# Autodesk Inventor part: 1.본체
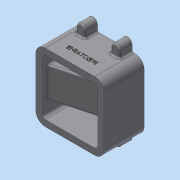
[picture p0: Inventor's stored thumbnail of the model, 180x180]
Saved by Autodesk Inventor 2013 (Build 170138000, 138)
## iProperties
Created: 2018-01
Part Number: 1.본체
Material: 일반
Document SubType Name: Modeling
Designer: dgall
Density: 1 g/cm^3
Author: dgall
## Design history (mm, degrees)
sketch "스케치1"
  geometry: L1 (-55, 55)-(55, 55); L2 (55, 55)-(55, -55); L3 (55, -55)-(-55, -55); L4 (-55, -55)-(-55, 55); 3 further points
  constraints: 8 end point, 2 midpoint, 2 parallel, 2 perpendicular, 1 horizontal, 1 horizontal alignment, 1 vertical alignment
  dimensions: "d1" = 110 distance of L1.start L1.end
extrude "돌출1" new body sketch "스케치1" distance "d3" = 65; taper "d4" = 0 deg
sketch "스케치2"
  geometry: L1 (-55, -55)-(55, -55) reference; L2 (55, -55)-(55, 55) reference; L3 (55, 55)-(-55, 55) reference; L4 (-55, 55)-(-55, -55) reference; L5 (-45, 45)-(45, 45); L6 (45, 45)-(45, -45); L7 (45, -45)-(-45, -45); L8 (-45, -45)-(-45, -25); L9 (-45, -25)-(35, -25); L10 (35, -25)-(35, 25); L11 (35, 25)-(-45, 25); L12 (-45, 25)-(-45, 45); 1 further point
  constraints: 16 end point, 6 parallel, 2 perpendicular, 1 collinear, 1 vertical alignment
  dimensions: "d5" = 10 distance between parallel lines of L4 L12; "d6" = 20 distance between parallel lines of L2 L10; "d7" = 10 distance between parallel lines of L2 L6; "d8" = 10 distance between parallel lines of L1 L7; "d9" = 10 distance between parallel lines of L3 L5; "d10" = 50 distance between parallel lines of L9 L11
extrude "돌출2" cut sketch "스케치2" distance "d11" = 65; taper "d12" = 0 deg
sketch "스케치3"
  geometry: L1 (80, -65)-(0, -65) reference; L2 (80, 0)-(80, -65) reference; L3 (0, -65)-(0, -56.436); L4 (0, -56.436)-(80, -35); L5 (-10, -65)-(-10, 0) reference; 1 further point
  constraints: 4 end point, 2 point on line, 1 perpendicular
  dimensions: "d13" = 30 distance of L1.start L4.end; "d14" = 105 deg angle of L3 L4; "d15" = 10 distance between parallel lines of L5 L3
extrude "돌출3" cut sketch "스케치3" distance "d16" = 65; taper "d17" = 0 deg
node "작업 평면1"
sketch "스케치4"
  geometry: L1 (0, 0)-(0, -56.436) reference; L2 (100, 0)-(-10, 0) reference; L3 (-10, 0)-(100, 0); L4 (-10, 0)-(-10, -7.5); L5 (-10, -7.5)-(9, -7.5); L6 (9, -7.5)-(9, -16); L7 (9, -16)-(23, -16); L8 (23, -16)-(23, -20); L9 (23, -20)-(70, -20); L10 (70, -20)-(70, -15); L11 (70, -15)-(75, -15); L12 (75, -15)-(75, 0); 1 further point
  constraints: 20 end point, 6 parallel, 3 perpendicular, 1 collinear, 1 point on line
  dimensions: "d18" = 15 diameter of L5 L2; "d19" = 32 diameter of L7 L2; "d20" = 40 diameter of L9 L2; "d21" = 30 diameter of L11 L2; "d22" = 5 distance of L10.end L11.end; "d23" = 47 distance of L8.end L9.end; "d24" = 14 distance of L6.end L7.end; "d25" = 19 distance of L4.end L5.end
revolve "회전1" sketch "스케치4" stored, may be unused: angle "d26" = 90 deg
sketch "스케치5"
  geometry: L1 (23, 0)-(70, 0) reference; L2 (23, 0)-(23, 0) reference; L3 (70, 0)-(23, 0) reference; L4 (70, 0)-(70, 0) reference; L5 (23, -20)-(70, -20) reference; L6 (-10, -65)-(-10, 0) reference; L7 (28, -25.757)-(-10, -35.939); L8 (-10, -53.939)-(65, -33.843); L9 (80, -35)-(0, -56.436) reference; L10 (70, -20)-(70, 0) reference; L11 (28, -25.757)-(28, 0); L12 (65, -33.843)-(65, 0); L13 (23, -20)-(23, 0) reference; 1 further point
  constraints: 8 end point, 4 point on line, 3 parallel, 1 perpendicular
  dimensions: "d28" = 18 distance of L8.start L7.end; "d29" = 5 distance between parallel lines of L9 L8; "d31" = 5 distance between parallel lines of L12 L10; "d32" = 5 distance between parallel lines of L13 L11
extrude "돌출4" cut sketch "스케치5" stored distance "d33" = 30; taper "d34" = 0 deg
fillet "모깎기1" dims "d35" = 3
fillet "모깎기2" dims "d36" = 3
fillet "모깎기3" dims "d37" = 3
fillet "모깎기4" dims "d38" = 3
fillet "모깎기5" dims "d39" = 15
sketch "스케치6"
  geometry: L1 (40, 55)-(-40, 55) reference; L2 (-55, 40)-(-55, 7.5) reference; L3 (-35.5, 65)-(-35.5, 55); L4 (-20.5, 65)-(-20.5, 55); L5 (20.5, 65)-(20.5, 55); L6 (35.5, 65)-(35.5, 55); A1 r 7.5 centre (-28, 65) between (-35.5, 65) and (-20.5, 65); A2 r 7.5 centre (28, 65) between (20.5, 65) and (35.5, 65); 1 further point
  constraints: 8 end point, 4 perpendicular, 4 point on circle, 4 point on line, 4 tangent, 2 centre point, 1 horizontal alignment
  dimensions: "d40" = 15 diameter of A1; "d41" = 15 diameter of A2; "d42" = 27 distance from line of L2 A1.centre; "d43" = 56 distance of A1.centre A2.centre; "d44" = 10 distance from line of L1 A2.centre
extrude "돌출5" join sketch "스케치6" distance "d45" = 20; taper "d46" = 0 deg
node "작업 평면2"
fillet "모깎기6" dims "d54" = 3
fillet "모깎기7" dims "d55" = 3
fillet "모깎기8" dims "d56" = 1
chamfer "모따기1" distance "d57" = 1; stored, may be unused: second distance "d58" = 2, angle "d59" = 45 deg
chamfer "모따기2" distance "d60" = 1; stored, may be unused: second distance "d61" = 2, angle "d62" = 45 deg
fillet "모깎기9" dims "d63" = 5
sketch "스케치8"
  geometry: L1 (80, 0)-(0, 0) reference; L2 (-15, 65)-(-15, 0) reference; 2 further points
  constraints: 1 other
  dimensions: "d66" = 55 distance from line of L2 point (40, 20); "d67" = 20 distance from line of L1 point (40, 20)
feature "엠보싱1" sketch "스케치8" dims "d1" = 110, "d5" = 10, "d6" = 20, "d7" = 10, "d8" = 10, "d9" = 10, "d10" = 50, "d68" = 0.5, "d69" = 0
fillet "모깎기12" dims "d70" = 3
fillet "모깎기13" dims "d71" = 3
sketch "스케치9"
  geometry: A1 r 7.5 centre (-28, -65) between (-35.5, -65) and (-20.5, -65) reference; A2 r 7.5 centre (28, -65) between (20.5, -65) and (35.5, -65) reference; A3 r 7.5 centre (28, 65) between (35.5, 65) and (20.5, 65) reference; A4 r 7.5 centre (-28, 65) between (-20.5, 65) and (-35.5, 65) reference; 1 further point
hole "구멍2" sketch "스케치9" at (28, 65), (-28, 65), (-28, -65), (28, -65) diameter "d72" = 3.242; stored, may be unused: countersink angle "d76" = 90 deg, drill point angle "d78" = 118 deg; dims "d73" = 9, "d74" = 4, "d75" = 2, "d77" = 11
node "솔리드1"
mirror "대칭1"
node "투영된 루프1"
